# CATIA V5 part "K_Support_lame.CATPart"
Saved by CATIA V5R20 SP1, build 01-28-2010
Part number: reglage_lame_coupe
Bounding box of the stored display mesh (mm): x -7 to 7, y -7 to 7, z 0 to 55
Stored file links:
  G:\Khaled_CFAO_2011\SIL\SIL_GR1\mroland\Khaled\CAD_CATIA_Modifie\K_Support_lame.CATPart
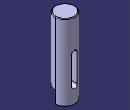
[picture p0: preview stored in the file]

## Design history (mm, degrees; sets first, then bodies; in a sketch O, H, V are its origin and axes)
Parameters
  diam_support_lame = 14 mm
Set1
  Sketch1 on xy-plane, origin (0, 0, 0), H (1, 0, 0), V (0, 1, 0)
    circle A1 centre (0, 0) radius 7
    radius A1 = 7
Body1 (main body)
  Pad1: profile Sketch1, direction (0, 0, 1), length 55
  Sketch2 on zx-plane, origin (0, 0, 0), H (-1, 0, 0), V (0, 0, 1)
    construction line L1 (0, 12) -> (0, 32)
    point P1 (0, 12)
    point P2 (0, 32)
    line L2 (-2, 12) -> (-2, 32)
    line L3 (2, 32) -> (2, 12)
    arc A1 centre (0, 32) radius 2 from (-2, 32) to (2, 32) cw
    arc A2 centre (0, 12) radius 2 from (2, 12) to (-2, 12) cw
    reference projected line E1 (-7, 55) -> (7, 55) from edge [face of Pad1 from Sketch1.A1 | end face of Pad1]
    distance L2 L3 = 4
    length L2 = 20
    distance P2 E1 = 23
    coincidence: P1 V, L1 V
    vertical: L1 V
    tangency: A1 L2, A2 L2, A1 L3, A2 L3
  Pocket1: profile Sketch2, direction (0, -1, 0), length 10, mirrored extent
  Chamfer1: length 0.5, angle 45, on edge [start face of Pad1 | face of Pad1 from Sketch1.A1]
  Chamfer2: length 0.5, angle 45, on edge [face of Pad1 from Sketch1.A1 | end face of Pad1]
  Sketch3 on start face of Pad1, origin (0, 0, 0), H (1, 0, 0), V (0, -1, 0)
    point P1 (-8, 0)
    line L1 (-8, 0) -> (8, 0)
    arc A1 centre (0, 0) radius 8 from (8, 0) to (-8, 0) ccw
    point P3 (0, 0)
    point P4 (0, 8)
    reference projected circle E1 centre (0, 0) radius 7 from edge [face of Chamfer1 | face of Pad1 from Sketch1.A1]
    radius A1 = 8
    coincidence: P1 H, A1 P4, P4 V
    horizontal: L1 H
    concentricity: P3 E1
  Pocket2: profile Sketch3, direction (0, 0, 1), length 9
